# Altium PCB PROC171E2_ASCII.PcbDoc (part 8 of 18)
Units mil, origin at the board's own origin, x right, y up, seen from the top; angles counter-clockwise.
Board outline 7700 x 2300 mil, 6 copper layers (Top Layer, GND 1, SIG 1, SIG 2, GND 2, Bottom Layer), stack 61.062 mil thick; 938 components, 688 nets, 11933 pads, 1723 vias.
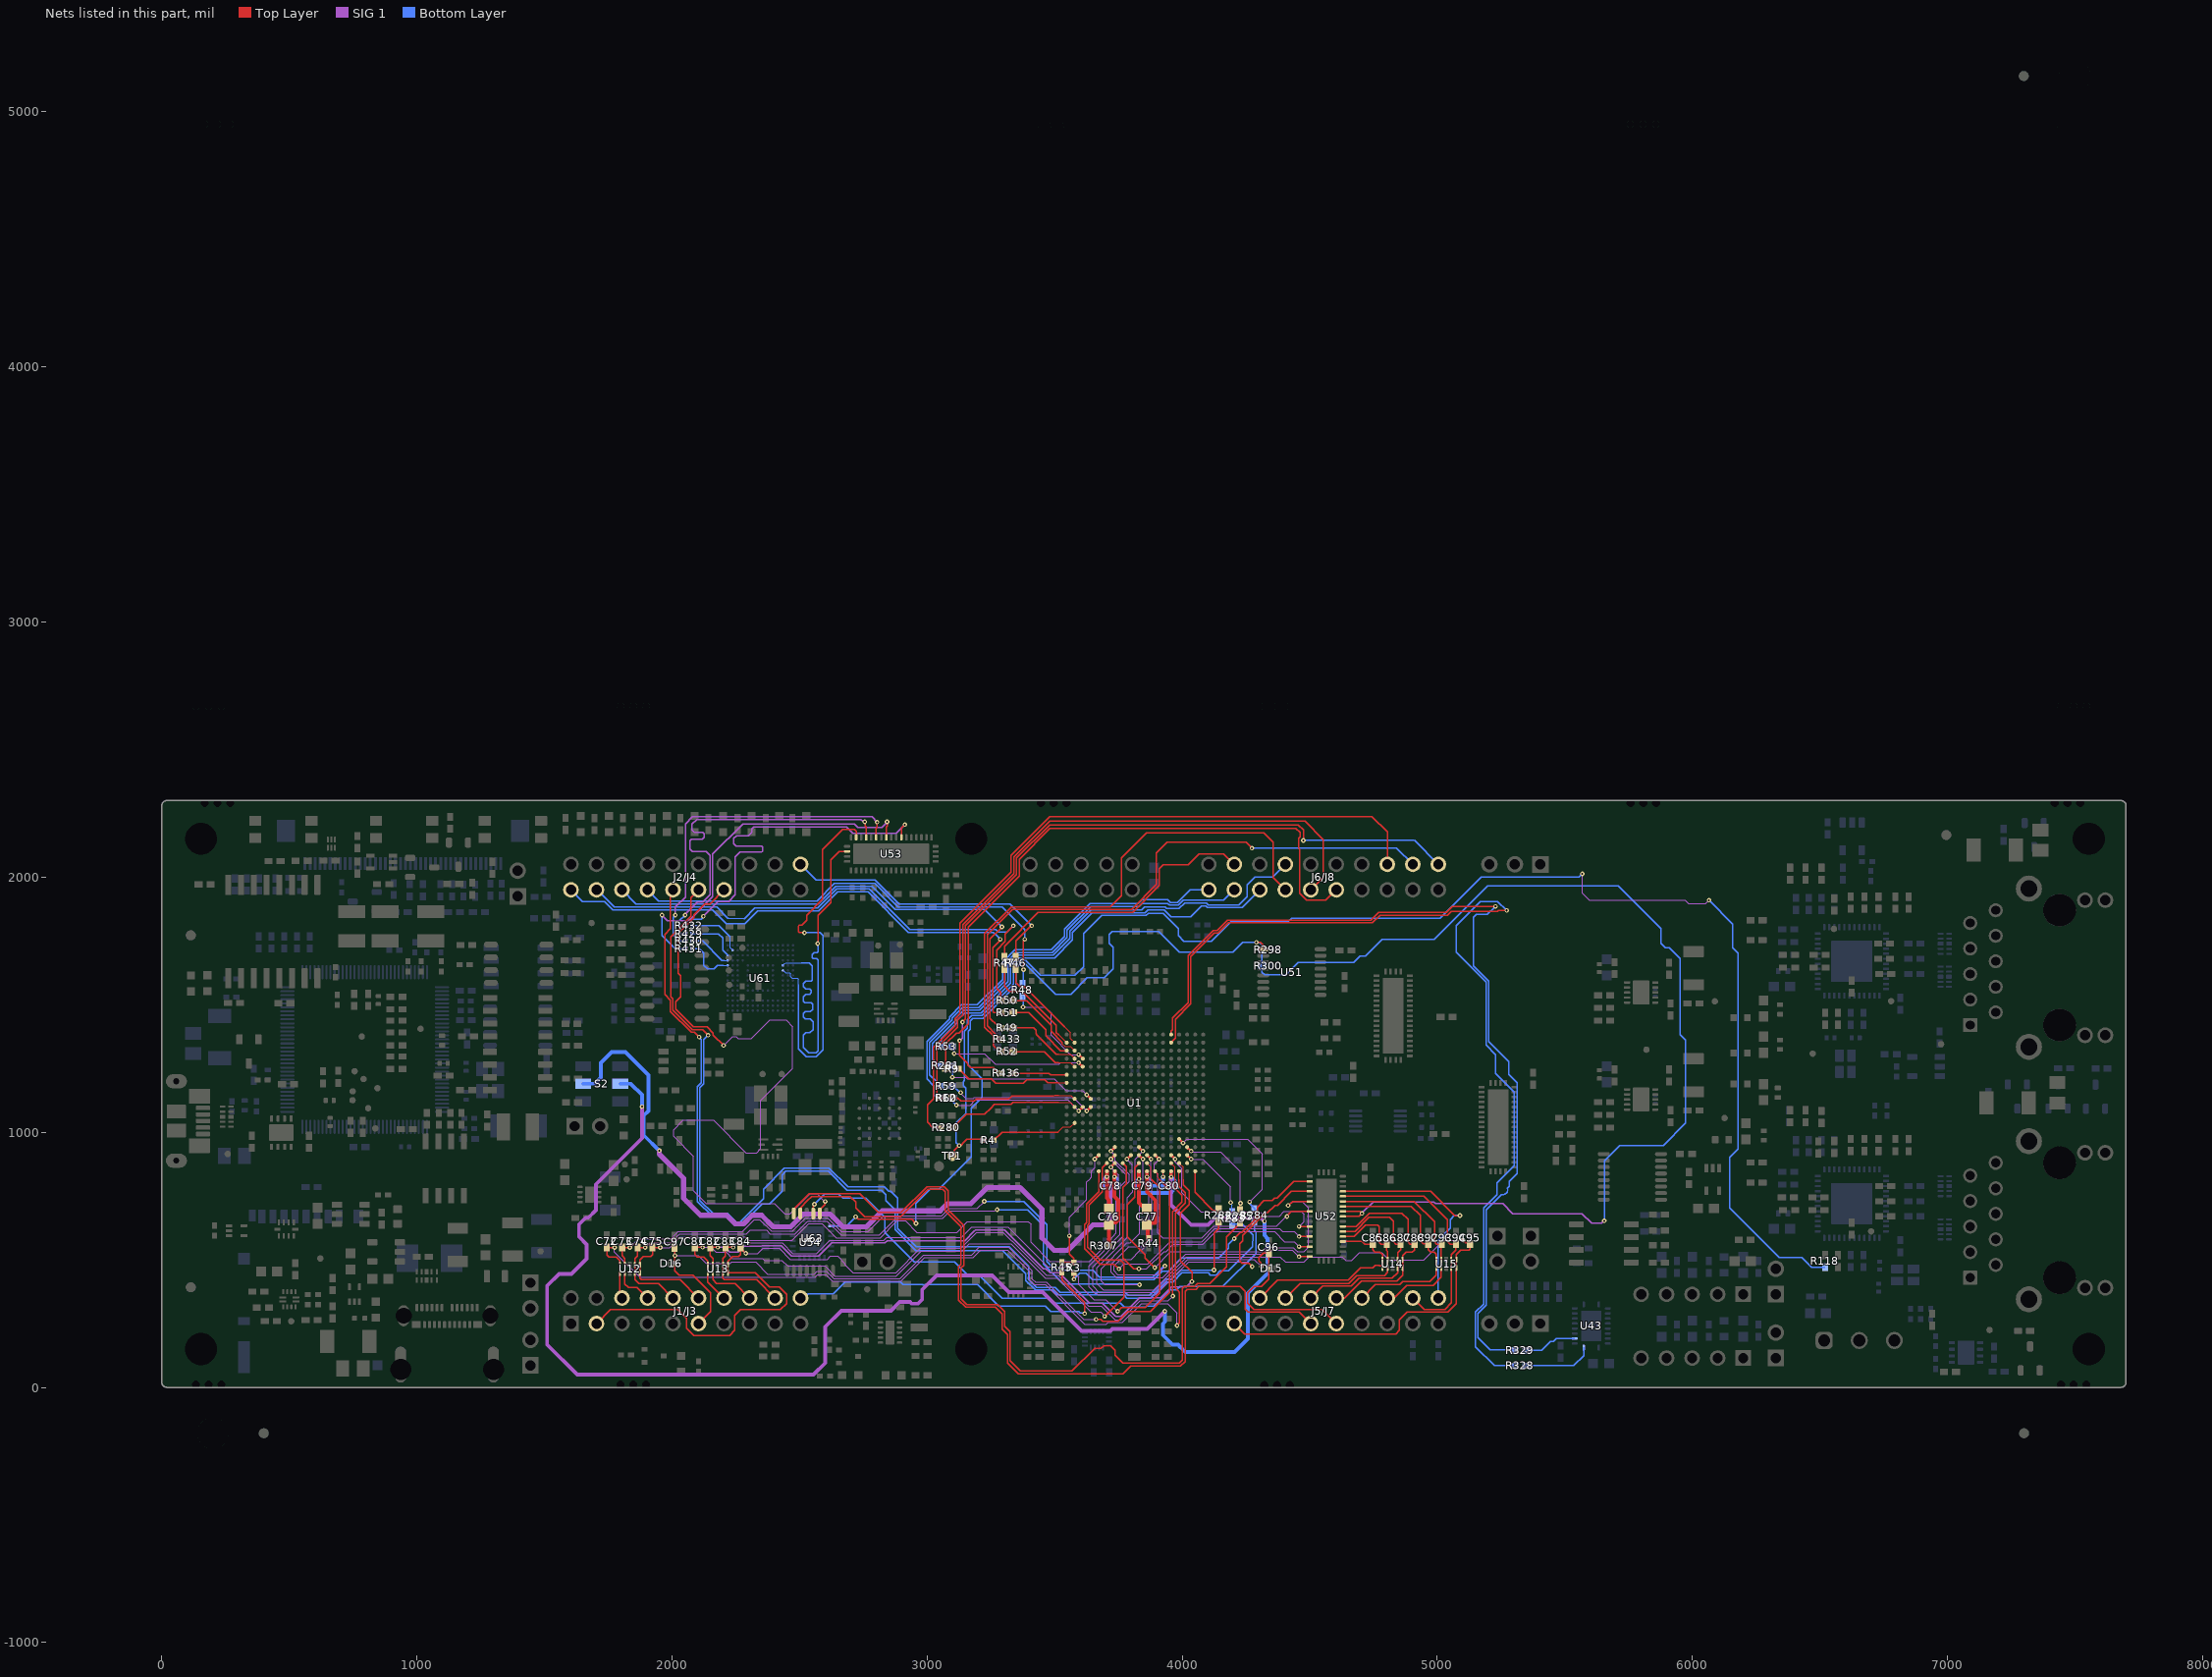
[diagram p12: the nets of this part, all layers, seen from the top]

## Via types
v1: diameter 18, hole 8, Top Layer to Bottom Layer, tented both sides, 1592 vias
v2: diameter 19.68, hole 7.87, Top Layer to Bottom Layer, tented both sides, 104 vias
v3: diameter 19.68, hole 7.87, Top Layer to Bottom Layer, 24 vias
v4: diameter 18, hole 8, Top Layer to Bottom Layer, 3 vias

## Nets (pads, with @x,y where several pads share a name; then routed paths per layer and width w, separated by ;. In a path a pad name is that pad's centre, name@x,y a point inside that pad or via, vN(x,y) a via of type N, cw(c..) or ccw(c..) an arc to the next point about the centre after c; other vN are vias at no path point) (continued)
AM263P_ADC0_AIN0: C72.1 J1/J3.23 U1.V15 U12.1 U12.10 | length 3479.2
  Top Layer w4: 3988.08,815.87 U1.V15@3988.08,847.36
  Top Layer w5.3: v1(1775,548.33) C72.1@1745,548.33 1745,519.48 1753.65,510.82 1781.73,510.82 1795.63,496.93 U12.10@1795.63,480.91 U12.1@1795.63,448.04 1795.63,358.54 J1/J3.23@1804.17,350 ; v1(3980,242.47) 3989.69,252.17 3989.69,373 3983.32,379.37 3972.78,389.91 3972.78,683.06 4012.02,722.3 4012.02,763.67 3988.08,787.62 3988.08,815.87
  SIG 1 w4.75: v1(1775,548.33) 1775,530.95 1873.95,432 2560.61,432 2571.02,442.4 2603.11,442.4 2629.31,416.21 2898.62,416.21 2990.57,508.16 3180.34,508.16 3210.71,538.54 3316.31,538.54 3401.85,453 3401.85,420.82 3420.39,402.28 3463.11,402.28 3618.67,246.72 3702,246.72 3709.39,254.12 3765.97,254.12 3840.62,328.77 3943.59,328.77 3980,292.36 v1(3980,242.47)
AM263P_ADC0_AIN1: C82.1 J1/J3.28 U1.U15 U13.2 U13.9 | length 2981.8
  Top Layer w4: U1.U15@3988.08,878.86 4003.83,863.11 4003.83,815.87
  Top Layer w5.3: v1@2180,548.85 C82.1@2150,548.85 2150,516.35 2160.31,506.03 U13.9@2160.31,481.44 U13.2@2160.31,448.56 2160.31,421.62 2175,406.94 2247.24,406.94 J1/J3.28@2304.17,350 ; 4003.98,815.87 4003.98,794.2 4028.17,770.01 4028.17,716.33 3993.84,681.99 3993.84,495.65 4038.32,451.17 4038.32,415.19 v1(4037.93,414.81)
  SIG 1 w5.3: v1(2180,548.85) 2207.48,548.85 2227,529.33 2258.52,529.33 2282.25,553.06 2350.56,553.06 2353.07,555.57 2428.12,555.57 2469.39,514.3 2574.61,514.3 2626.21,565.9 2834.71,565.9 2844.1,575.28 3148.64,575.28 3185.4,612.05 ; 3185.43,612.05 3190.42,617.03 3304.18,617.03 3423.64,497.58 3455.96,465.25 3466.49,465.25 3482.34,449.4 3517.17,449.4 3558.03,408.53 3558.81,408.53 3637.77,329.58 3687.14,329.58 3729.6,287.11 3729.6,286.79 3736.94,279.45 3738.15,279.45 3739.01,278.59 3759.86,278.59 3832.89,351.62 3915.55,351.62 3957.51,393.58 4016.7,393.58 v1(4037.93,414.81)
AM263P_ADC0_AIN2: U1.T14 U52.32 | length 790.2
  Top Layer w5.3: v1(4458.39,630.63) U52.32@4500.04,630.63
  Top Layer w10: U1.T14@3956.58,910.35 v1(3972.33,894.61)
  SIG 1 w4.75: v1(3972.33,894.61) 3972.33,885.08 3999.43,857.98 3999.43,762.5 4073.08,688.86 4305.29,688.86 4323.32,670.83 4381.38,670.83 4399.8,689.25 4465.75,689.25 4477.03,677.97 4477.03,649.27 v1(4458.39,630.63)
AM263P_ADC0_AIN2_LIN1_TXD: C88.1 J5/J7.66 U14.5 U14.6 U52.7 | length 857.5
  Top Layer w5.3: J5/J7.66@4604.17,350 4635.87,350 4703.06,417.19 4841.67,417.19 4864.37,439.89 U14.5@4864.37,467.68 U14.6@4864.37,500.55 4864.37,516.12 4877.56,529.31 4902.1,529.31 4910,537.21 4910,560.42 C88.1@4911.11,561.53 4893.47,561.53 4885,570 4885,658.91 4861.58,682.33 4734.12,682.33 4682.42,630.63 U52.7@4629.96,630.63
AM263P_ADC0_AIN3: C84.1 J1/J3.2 U1.U14 U13.5 U13.6 | length 3919.4
  Top Layer w4: U1.U14@3956.58,878.86 3972.4,863.04 3972.4,816.09 3972.18,815.87
  Top Layer w5.3: J1/J3.2@1704.17,250 1759.17,305 2022.85,305 2057.7,270.15 2057.7,231.07 2085.4,203.37 2226.16,203.37 2246.16,223.37 2246.16,281.95 2269.09,304.88 2424.91,304.88 2449.05,329.02 2449.05,363.97 2420.06,392.97 2382.1,392.97 2326.5,448.56 U13.5@2219.37,448.56 U13.6@2219.37,481.44 2219.37,494.53 2238.22,513.38 2261.62,513.38 2269,520.76 C84.1@2269,544.91 ; C84.1@2269,548.85 C84.1@2269,544.91 ; v1(2289.41,525.59) 2288.33,525.59 C84.1@2269,544.91 ; v1(3963.8,357.77) 3962.18,359.38 3962.18,688.13 3999.52,725.47 3999.52,753.11 3972.18,780.46 3972.18,815.87
  SIG 1 w4.75: v1(2289.41,525.59) 2290.99,524.01 2336.11,524.01 2357.35,545.25 2420.66,545.25 2463.73,502.18 2609.18,502.18 2621.48,514.47 2649.1,514.47 2679.36,484.22 2679.36,479.45 2709.61,449.2 2878,449.2 2973.79,544.99 3132.98,544.99 3194.7,606.71 3297.81,606.71 3330.67,573.85 3332.76,573.85 3467.54,439.08 3512.89,439.08 3632.71,319.25 3682.55,319.25 3707.8,293.99 cw(c3696.42,278.47) 3711.94,289.86 3737.63,264.17 3760.04,264.17 3834.87,338.99 3944.78,338.99 3963.56,357.77 v1(3963.8,357.77)
AM263P_ADC1_AIN0: C73.1 J1/J3.24 U1.T11 U12.2 U12.9 | length 3536.9
  Top Layer w5.3: v1(1835,548.33) C73.1@1805,548.33 1805,515.82 1815.31,505.51 1815.31,405.72 1830,391.04 1863.14,391.04 J1/J3.24@1904.17,350
  Top Layer w10: U1.T11@3862.09,910.35 v1(3877.84,894.61)
  SIG 1 w4.75: v1(1835,548.33) 1868.5,581.83 1994.64,581.83 2024.06,611.25 2276.97,611.25 2322.58,656.86 2344.56,656.86 2389.37,612.05 2472.24,612.05 2522.24,662.05 2612.21,662.05 2662.21,612.05 2662.78,612.05 2663.06,611.76 2769.52,611.76 2830.68,672.92 3058.06,672.92 3086.52,701.38 3196.54,701.38 v1(3224.39,729.23) ; v1(3877.84,894.61) 3877.84,813.9 3879.92,811.83 3881.31,810.44 3881.31,806.5 3881.26,782 3880.81,578.66 3880.8,576.7 3841.02,536.92 3835.88,536.92 3799.98,501.02 3757.27,501.02 3738.02,481.78 3736.78,480.54 3732.87,476.63 3732.87,456.31 3747.29,441.9 3900.58,441.9 3932.06,473.38 v1(3932.06,475.69)
  Bottom Layer w5.3: v1(3224.39,729.23) 3378.99,729.23 3469.57,638.65 3469.57,493.7 3504.61,458.66 3649.62,458.66 3673.9,434.38 3675.46,432.83 3732.26,432.83 ccw(c3735.54,452.07) 3738.82,432.83 3778.57,432.83 ccw(c3781.85,452.07) 3785.13,432.83 3884.32,432.83 3922.93,471.44 3924.38,471.44 3928.62,475.69 v1(3932.06,475.69)
AM263P_ADC1_AIN1: C83.1 J1/J3.29 U1.U11 U13.4 U13.7 | length 2844.6
  Top Layer w4: U1.U11@3862.09,878.86 3877.84,863.11 3877.84,818.36 3880.34,815.87
  Top Layer w5.3: v1@2240,548.85 C83.1@2210,548.85 2210,515.31 2199.68,505 U13.7@2199.68,481.44 U13.4@2199.68,448.56 2199.68,428.15 2205,422.84 2331.34,422.84 J1/J3.29@2404.17,350 ; v1(3747.1,298.12) 3761.59,312.6 3854.57,312.6 3912.24,370.28 3912.24,600.79 3912.15,600.88 3912.15,717.06 3912.24,717.15 3912.24,782 3912.24,783.96 3880.34,815.87
  SIG 1 w4.75: v1(2240,548.85) 2257.57,566.42 2296.49,566.42 2296.98,565.94 2432.36,565.94 2473.67,524.63 2567.66,524.63 2619.26,576.22 2830.43,576.22 2841.61,587.4 3134.6,587.4 3175.66,628.47 3317.88,628.47 3473.79,472.55 3554.06,472.55 3574.45,452.16 3594.84,431.77 3594.84,403.13 3653.65,344.32 3700.9,344.32 v1(3747.1,298.12)
AM263P_ADC1_AIN2: U1.T12 U52.29 | length 973.5
  Top Layer w5.3: v1(4411.13,670) 4411.13,673.36 4427.46,689.69 U52.29@4500.04,689.68
  Top Layer w10: U1.T12@3893.59,910.35 v1(3909.34,894.61)
  SIG 1 w4: 3890.46,850 3890.46,874.7 3909.34,893.58 v1(3909.34,894.61)
  SIG 1 w4.75: 3890.46,850 3904.9,835.56 3904.9,605 3923.79,586.11 4077.9,586.11 4123.81,632.03 4369.81,632.03 4407.78,670 v1(4411.13,670)
AM263P_ADC1_AIN2_SDFM0_D2: C92.1 J5/J7.67 U15.1 U15.10 U52.11 | length 926.3
  Top Layer w5.3: U52.11@4629.96,709.37 4897.79,709.37 4933.44,673.72 4933.44,574.11 4945.18,562.38 C92.1@4965,562.38 4965,540 4975,530 4988.59,530 4996.03,522.56 U15.10@4996.03,500.69 U15.1@4996.03,467.82 4996.03,440.53 4970.21,414.7 4865.21,414.7 4852.93,402.43 4756.6,402.43 J5/J7.67@4704.17,350
AM263P_ADC1_AIN3: C97.1 D16.1 J1/J3.6 U1.V12 | length 3134.9
  Top Layer w4: U1.V12@3893.59,847.36 3905,835.95 3905,822.02 3911.16,815.87
  Top Layer w5.3: C97.1@2010,547.76 2011.57,546.19 v1(2011.57,516.57) 2011.04,516.04 2011.04,490.55 2010.51,490.03 2010.51,457.6 2028.08,440.03 2082.25,440.03 2151,371.28 2151,296.83 J1/J3.6@2104.17,250 ; v1(3662.42,266.64) 3680.64,266.64 3688.33,258.95 3748.71,258.95 3787.78,298.02 3876.43,298.02 3951.58,373.17 3951.58,775.44 3911.16,815.87
  SIG 1 w4.75: v1(2011.57,516.57) 2102.93,516.57 2134.4,485.1 2227.96,485.1 2233.72,490.87 2327.69,490.87 2374.29,444.26 2557.26,444.26 2568.43,455.43 2604.93,455.43 2634.1,426.26 2894.45,426.26 2986.41,518.21 3174.31,518.21 3204.95,548.85 3320.22,548.85 3411.9,457.17 3411.9,424.98 3424.55,412.33 3467.27,412.33 3612.97,266.64 v1(3662.42,266.64)
AM263P_ADC2_AIN0: C74.1 J1/J3.25 U1.R10 U12.4 U12.7 | length 3383.5
  Top Layer w5.3: v1(1895,548.33) C74.1@1865,548.33 1865,514.79 1854.68,504.48 U12.7@1854.68,480.91 U12.4@1854.68,448.04 1854.68,422.25 1870,406.94 1947.24,406.94 J1/J3.25@2004.17,350
  Top Layer w10: U1.R10@3830.6,941.85 v1(3846.35,926.1)
  SIG 1 w4.75: v1(1895,548.33) 1914.25,567.58 1995.86,567.58 2029.49,601.2 2291.98,601.2 2307.39,616.62 2370.59,616.62 2385.21,602 2481.74,602 2531.74,652 2608.04,652 2662.39,597.65 2812.49,597.65 2818.52,603.69 2818.57,603.74 2879.32,662.87 3062.22,662.87 3090.68,691.33 3266.2,691.33 3271.36,696.5 v1(3274.95,696.5) ; v1(3832.75,402.43) 3696.51,402.43 3682.23,416.7 3682.23,464.48 3783.89,566.14 3796.1,566.14 3832.75,602.79 3832.75,778.4 3815,796.15 3815,894.76 v1(3846.35,926.1)
  Bottom Layer w5.3: v1(3274.95,696.5) 3393.99,696.5 3455.71,634.78 3455.71,484.14 3535.57,404.28 3830.9,404.28 v1(3832.75,402.43)
AM263P_ADC2_AIN1: U1.T10 U52.38 | length 1406.9
  Top Layer w5.3: v1(4458.39,512.52) U52.38@4500.04,512.52
  Top Layer w10: U1.T10@3830.6,910.35 v1(3846.35,894.61)
  SIG 1 w4: v1(3846.35,894.61) 3847,893.95 3847,815.87
  SIG 1 w4.75: 3847,815.87 3847,799.35 3870.75,775.6 3870.75,581.13 3841.51,551.89 3791.41,551.89 3722.31,482.79 3722.31,450.92 3742.28,430.95 3922.89,430.95 4013.85,521.91 4316.43,521.91 4331.45,536.92 4431.92,536.92 4456.32,512.52 v1(4458.39,512.52)
AM263P_ADC2_AIN1_MCAN5_RX: C85.1 J5/J7.63 U14.1 U14.10 U52.4 | length 781.9
  Top Layer w5.3: J5/J7.63@4304.17,350 4374.17,420 4650.72,420 4698.4,467.68 4746.98,467.68 4756.74,477.44 4772.92,477.44 4774.55,475.8 4784.34,475.8 4784.34,468.97 U14.1@4785.63,467.68 ; U52.4@4629.96,571.57 4705.59,571.57 4715.63,561.53 C85.1@4747.11,561.53 4747.11,538.93 4755.01,531.03 4774.59,531.03 4785.63,519.99 U14.10@4785.63,500.55 U14.1@4785.63,470.66
AM263P_ADC2_AIN2: U1.U10 U52.27 | length 1464.1
  Top Layer w5.3: U1.U10@3830.6,878.86 3813.63,861.89 3813.63,745.2 3785.48,717.06 3785.48,589.52 3854.78,520.22 3854.78,507.45 v1(3892.72,469.51) ; v1(4415.63,712.91) 4416.63,712.91 4432.77,729.06 U52.27@4500.04,729.06
  SIG 1 w4.75: v1(3892.72,469.51) 3955.17,531.96 4312.27,531.96 4328.49,548.18 4435.22,548.18 4442.78,540.62 ccw(c4458.39,551.89) 4447.12,536.28 4450.24,533.16 4451.63,531.77 4477.64,531.77 4495.75,549.88 4495.75,703.31 4470,729.06 4432.77,729.06 4429.21,725.5 v1(4415.63,712.91)
AM263P_ADC2_AIN2_SDFM0_CLK2: C93.1 J5/J7.68 U15.2 U15.9 U52.12 | length 879.5
  Top Layer w5.3: U52.12@4629.96,729.06 4909.46,729.06 4990,648.51 4990,570 4998.33,561.67 C93.1@5017.97,561.67 5015.48,559.18 5015.48,500.94 U15.9@5015.72,500.69 U15.2@5015.72,467.82 5015.72,432.26 4983.46,400 4879.37,400 4829.37,350 J5/J7.68@4804.17,350
AM263P_ADC2_AIN3: C95.1 J5/J7.42 U1.T9 U15.5 U15.6 | length 3425.2
  Top Layer w5.3: J5/J7.42@4204.17,250 4245.85,208.32 4836.86,208.32 4852.06,223.52 4852.06,265 4881.8,294.74 5041.07,294.74 5074.77,328.45 U15.5@5074.77,467.82 U15.6@5074.77,500.69 5074.77,519.94 5092.55,537.72 5123.8,537.72 5128.54,542.46 C95.1@5128.54,561.67 5124.09,566.12 5111.88,566.12 v1(5101.72,576.29)
  Top Layer w10: v1(3783.35,894.61) U1.T9@3799.1,910.35
  SIG 1 w4.75: v1(3783.35,894.61) 3804.95,873.01 3804.95,791.99 3806.82,790.12 3806.82,766.43 3785,744.61 3785,587.4 3665.68,468.08 3665.68,406.97 3689.91,382.74 3888.69,382.74 3926.85,420.9 3927.05,420.9 4018.01,511.86 4384.34,511.86 4404.26,491.94 4478.29,491.94 4498.01,511.66 4627.69,511.66 4641.95,497.4 4664.13,497.4 4695.15,528.42 4781.94,528.42 4810.84,499.52 4947.63,499.52 5024.4,576.29 v1(5101.72,576.29)
AM263P_ADC3_AIN0: C75.1 J1/J3.26 U1.U7 U12.5 U12.6 | length 2824
  Top Layer w5.3: v1(1954,548.33) C75.1@1924,548.33 1924,520.24 1916.62,512.86 1887.02,512.86 1874.37,500.2 U12.6@1874.37,480.91 U12.5@1874.37,448.04 1874.37,428.47 1880,422.84 2031.34,422.84 J1/J3.26@2104.17,350
  Top Layer w10: v1(3720.36,863.11) U1.U7@3736.11,878.86
  SIG 1 w4: v1@3720.36,862.49 v1(3720.36,863.11)
  SIG 1 w4.75: v1(1954,548.33) 1990.82,548.33 2032.75,590.25 2286.87,590.25 2301.14,575.99 2469.94,575.99 2535.9,641.95 2588.9,641.95 2596.8,634.06 2644.35,586.5 2817.16,586.5 2883.49,652.82 2914.87,652.82 2959.62,608.07 3116.64,608.07 3157.14,648.57 3397.39,648.57 3407.02,638.93 3407.02,567.96 3481,493.99 3637.06,493.99 3695.11,552.04 3741.83,604.69 3741.83,786.42 3750.08,794.67 3750.08,832.77 v1@3720.36,862.49
AM263P_ADC3_AIN1: U1.U8 U52.36 | length 1218
  Top Layer w5.3: U1.U8@3767.61,878.86 3782.13,864.33 3782.13,798.59 3768.05,784.5 3768.05,506.27 3809.61,464.7 v1(3830.03,464.7) ; v1(4458.39,551.89) U52.36@4500.04,551.89
  SIG 1 w4.75: v1(3830.03,464.7) 3860.69,464.7 3928.78,532.8 3936.72,532.8 3965.01,561.09 4081.3,561.09 4130.17,609.96 4136.7,609.96 4136.84,610.1 4362.33,610.1 4401.28,571.14 4439.14,571.14 v1(4458.39,551.89)
AM263P_ADC3_AIN1_MCAN5_TX: C86.1 J5/J7.64 U14.2 U14.9 U52.5 | length 812.1
  Top Layer w5.3: J5/J7.64@4404.17,350 4462.03,407.86 4653.57,407.86 4684.1,438.39 4792.53,438.39 4805.31,451.17 U14.2@4805.31,467.68 U14.9@4805.31,500.55 4805.31,533.2 4802.11,536.4 C86.1@4802.11,561.53 4780.42,561.53 4772.38,569.58 4772.38,630 4765.84,636.54 4719.02,636.54 4673.74,591.26 U52.5@4629.96,591.26
AM263P_ADC3_AIN2: U1.T7 U52.25 | length 1819.4
  Top Layer w5.3: v1(4274.32,473.35) 4274,473.35 4262.17,485.18 4235.93,485.18 4226.54,494.58 4226.54,563.49 4237.5,574.46 4237.5,595.21 4325.55,683.26 4333.87,683.26 4364,713.38 4373.5,713.38 4428.54,768.43 U52.25@4500.04,768.43
  Top Layer w10: v1(3720.36,894.61) U1.T7@3736.11,910.35
  SIG 1 w4.75: v1(3720.36,894.61) 3720.36,893.05 3781.11,832.3 3781.11,811.39 3756.08,786.36 3756.08,598.79 3634.41,477.12 3634.41,392.96 3658.26,369.11 3664.2,369.11 3670.66,362.64 3897.22,362.64 4026.33,491.76 4255.91,491.76 v1(4274.32,473.35)
AM263P_ADC3_AIN2_SDFM0_D3: C94.1 J5/J7.69 U15.4 U15.7 U52.13 | length 987.1
  Top Layer w5.3: U52.13@4629.96,748.74 4948.18,748.74 5040.31,656.61 5040.31,573.23 5051.87,561.67 C94.1@5073,561.67 5073,538 5055.09,520.09 U15.7@5055.09,500.69 U15.4@5055.09,467.82 5055.09,331.25 5029.53,305.69 4948.48,305.69 J5/J7.69@4904.17,350
AM263P_ADC3_AIN3: C96.1 D15.2 J5/J7.46 U1.R7 | length 2087.9
  Top Layer w5.3: v1(4310.31,473.53) 4307.89,475.96 4307.89,487.83 4300.31,495.4 4300.31,508.74 4317.89,526.31 C96.1@4339.72,526.31 4339.72,467.6 D15.2@4338.78,466.66 4338.78,423.78 4310,395 4282.16,395 4257.41,370.25 4257.41,329.77 4281.66,305.53 4548.64,305.53 J5/J7.46@4604.17,250
  Top Layer w10: v1(3720.36,926.1) U1.R7@3736.11,941.85
  SIG 1 w4: v1(3720.36,926.1) 3736.86,909.61 3736.86,888.39 3791.97,833.28 3791.97,815.87 3791.97,808.04
  SIG 1 w4.75: 3791.97,808.04 3768.32,784.39 3768.32,590.88 3650,472.55 3650,397.52 3672.37,375.15 3683.29,375.15 3685.75,372.69 3893.06,372.69 4022.17,501.81 4282.04,501.81 v1(4310.31,473.53)
AM263P_ADC4_AIN0: C81.1 J1/J3.27 U1.U6 U13.1 U13.10 | length 2852.5
  Top Layer w5.3: v1@2120,548.85 C81.1@2090,548.85 2090,520 2098.65,511.35 2124.65,511.35 2140.63,495.36 U13.10@2140.63,481.44 U13.1@2140.63,448.56 2140.63,413.54 J1/J3.27@2204.17,350 ; v1(3696.42,278.47) 3771.65,353.7 3771.65,485.44 3757.09,500 3679.58,500 3629.29,550.3 3629.29,634.29 3635.93,640.93 3635.93,714.5 3687.64,766.21 3687.64,861.89 U1.U6@3704.61,878.86
  SIG 1 w4.75: v1(2120,548.85) 2152.78,548.85 2172.03,529.6 2212.13,529.6 2236.64,505.09 2355.91,505.09 2363.18,497.82 2430.85,497.82 2452.96,475.71 2598.87,475.71 2638.27,436.31 2879.32,436.31 2977.54,534.52 3136.92,534.52 3166.2,563.8 3288.62,563.8 ccw(c3290.44,582.96) 3292.26,563.8 3328.6,563.8 3463.88,428.52 3509.24,428.52 3643.25,294.5 3680.39,294.5 v1(3696.42,278.47)
AM263P_ADC4_AIN1: U1.V5 U52.34 | length 1318.7
  Top Layer w5.3: U1.V5@3673.12,847.36 3673.12,766.68 3625.33,718.89 3625.33,645.32 3618.69,638.68 3618.69,544.2 3680.24,482.64 3733.79,482.64 v1(3752.12,464.31) ; v1(4458.39,591.26) U52.34@4500.04,591.26
  SIG 1 w4.75: v1(3752.12,464.31) 3752.12,465.22 3770.85,483.95 3865.73,483.95 3952.91,571.14 4077.13,571.14 4127.98,621.98 4382.08,621.98 4393.55,610.51 4439.14,610.51 v1(4458.39,591.26)
AM263P_ADC4_AIN1_LIN1_RXD: C87.1 J5/J7.65 U14.4 U14.7 U52.6 | length 837
  Top Layer w5.3: J5/J7.65@4504.17,350 4551.43,397.26 4662,397.26 4692.53,427.79 4822.45,427.79 4844.69,450.03 U14.4@4844.69,467.68 U14.7@4844.69,500.55 4844.69,527.99 4856.7,540 C87.1@4856.7,561.53 4838.47,561.53 4827.2,572.8 4827.2,651.1 4812.48,665.82 4732.61,665.82 4677.73,610.94 U52.6@4629.96,610.94
AM263P_ADC_CAL0: U1.U16
AM263P_ADC_CAL1: U1.T15
AM263P_ADC_VREFHI_G01: C77.1 C79.1 C80.1 S2.2 U1.V10 U1.V14 | length 6106.6
  Top Layer w15: U1.V10@3830.6,847.36 3831.11,846.85 v1(3831.11,816.77) 3831.11,810.33 3830.6,809.82 3830.6,723.99 3841.97,712.62 3850.13,712.62 3853.51,709.23 C77.1@3853.51,701.07 ; v1(3956.58,825) U1.V14@3956.58,847.36
  SIG 1 w15: v1(1882.41,1100.31) 1882.41,976.67 1701.41,795.68 1701.41,783.58 cw(c1676.92,777.56) 1701.41,771.54 1701.41,740.27 cw(c1676.92,734.25) 1701.41,728.23 1701.41,693.97 1672.28,664.84 1661.43,664.84 1635.86,639.27 1635.86,590.25 1665.77,560.34 1665.77,503.94 1606.09,444.26 1557.23,444.26 1510.73,397.76 1510.73,167.42 1628.33,49.82 2555.01,49.82 2600.42,95.23 2600.42,237.51 2663.58,300.67 2858.14,300.67 2892.09,334.63 2933.05,334.63 2939.75,327.93 2964.08,327.93 2980.76,344.62 2980.76,382.28 3037.71,439.23 3254.42,439.23 3319.81,373.83 3452.61,373.83 3605.36,221.08 3719.49,221.08 3727.19,228.78 3862.37,228.78 v1(3931.79,298.19) ; v1(3956.58,825) 3956.01,824.43 3956.01,822.3 3955.63,821.92 3955.63,719.49 3956.05,719.06 3956.05,716.42 4035.38,637.09 4101.11,637.09 4128.47,664.46 4308.23,664.46 4317.03,655.65 4317.17,655.65 4321.54,651.28 v1(4322.35,651.28)
  Bottom Layer w15: S2.2@1797.54,1190 1839.19,1190 1882.41,1146.78 v1(1882.41,1100.31) ; v1(3831.11,816.77) 3823.14,808.8 3823.14,789.94 3825.13,789.94 3829.44,785.63 3829.44,771.54 3838.22,762.75 3955.21,762.75 3964,771.54 3964,785.63 3968.31,789.94 C80.1@3972.24,789.94 3972.24,809.34 v1(3956.58,825) ; v1(3931.79,298.19) 3931.79,257.01 3923.94,249.16 3923.94,204.82 3962.1,166.67 3984.03,166.67 3992.51,158.18 cw(c3979.12,137.82) 3999.49,151.21 4012.88,137.82 4204.86,137.82 4257.94,190.9 4257.94,355 4258.29,355.35 4258.29,369.71 4334.93,446.35 4334.93,583.65 4322.35,596.23 v1(4322.35,651.28)
AM263P_ADC_VREFHI_G2: C76.1 C78.1 S2.5 U1.V6 | length 3365.7
  Top Layer w15: U1.V6@3704.61,847.36 v1(3704.61,825) 3704.61,742.32 3713.32,733.62 3713.32,698.14 C76.1@3713.17,698
  SIG 1 w8: 3704.49,800.8 3707.05,798.24 ; v1@3704.49,824.87 v1(3704.61,825)
  SIG 1 w20: v1(1950.75,927.95) 1950.75,914.12 2045.27,819.6 2045.27,741.3 2112.03,674.54 2214.47,674.54 2247.99,641.02 2281.74,641.02 2315.26,674.54 2351.88,674.54 2396.69,629.72 2464.91,629.72 2514.92,679.72 2620.1,679.72 2670.39,629.44 2762.2,629.44 2824.25,691.49 3051.63,691.49 3079.45,719.31 3171.56,719.31 3235.35,783.1 3365.08,783.1 3450,698.18 3450,585.76 3498.56,537.2 3550.76,537.2 3650.66,637.09 3700.33,637.09 3715.62,652.38 3715.62,789.67 3707.05,798.24 ; 3704.49,800.8 v1@3704.49,824.87
  Bottom Layer w15: S2.5@1651.87,1190 1697.96,1190 1721.8,1213.85 1721.8,1272.05 1763.82,1314.08 1816.93,1314.08 1907.31,1223.69 1907.31,1083.75 1889.85,1066.3 1889.85,988.19 v1@1950.09,927.95 ; C78.1@3696.74,789.94 3696.74,817.13 v1(3704.61,825)
AM263P_ADC_VREFLO_G01: C77.2 C79.2 C80.2 R44.2 U1.V11 U1.V13 | length 450
  Top Layer w4: v1(3925.09,825) U1.V13@3925.09,847.36
  Top Layer w15: C77.2@3861.07,637.7 3868.69,645.32 3893.65,645.32 3894.93,646.6 3894.93,733.21 3862.67,765.48 3862.67,815.87 3862.67,824.43 v1(3862.09,825) U1.V11@3862.09,847.36 ; C77.2@3864.29,628.58 3864.29,597.52 3867.19,594.61 3867.19,586.76 R44.2@3869.54,584.42
  Bottom Layer w15: v1(3862.09,825) 3862.09,824.19 3868.43,817.85 C79.2@3868.43,789.94 C80.2@3925,789.94 3925,824.91 v1(3925.09,825)
AM263P_ADC_VREFLO_G2: C76.2 C78.2 R307.2 U1.V7 | length 362.7
  Top Layer w15: R307.2@3713.62,555 3713.17,555.45 3713.17,635.99 3724.37,647.19 3740.05,647.19 3748.83,655.98 3748.83,733.91 3734.71,748.04 3734.71,815.87 3734.71,825.81 3736.11,827.21 U1.V7@3736.11,847.36
  Bottom Layer w15: v1(3734.71,825) 3735.28,824.43 3736.68,824.43 3743.98,817.13 C78.2@3743.98,789.94
AM263P_BP_MUX_SEL: R298.2 R300.2 U51.1 U52.9 U52.10 U63.7 | length 7416.2
  Top Layer w5.3: v1(2720.04,668.83) 2730.64,658.23 2940.7,658.23 v1(2956.41,642.55) ; v1(4291.03,1744.24) 4306.84,1744.24 4317.8,1733.28 U51.1@4317.8,1717.48 ; U52.9@4629.96,670 4693.01,670 v1(4705,681.99) 4697.31,689.68 U52.10@4629.96,689.68
  SIG 1 w5.3: v1(4705,681.99) v1@4705.75,682.74 ; v1@4705.15,683.35 4748.36,726.56 4986.66,726.56 4993.16,720.06 5256.77,720.06 5296.35,680.48 5567.74,680.48 5605.21,643 5644.31,643 v1(5654.39,653.09)
  Bottom Layer w5.3: U63.7@2623.77,632.69 2683.9,632.69 v1(2720.04,668.83) ; v1@2956.39,642.57 2956.39,720.88 3011.71,776.2 3045.69,776.2 3173.69,904.21 3173.69,1094.74 3192.9,1113.95 3192.9,1114.06 3204.33,1125.49 3204.44,1125.49 3215.19,1136.24 3215.19,1209.93 3197.95,1227.17 ; 3197.82,1227.05 3161.21,1263.66 3161.21,1396.25 3169.22,1404.26 3169.22,1436.23 3179.91,1446.92 3219.93,1446.92 3348.77,1575.76 3348.77,1644.44 3366.83,1662.51 3382.13,1662.51 3503.4,1541.24 3562.92,1541.24 3627.8,1606.12 3694.35,1606.12 3729.57,1641.35 3729.57,1724.32 3713.62,1740.28 3713.62,1775.16 3725.58,1787.12 3909.07,1787.12 3989.71,1706.48 4199.68,1706.48 4237.44,1744.24 v1(4291.03,1744.24) 4291.19,1744.08 4302.68,1744.08 4312.89,1733.88 R300.2@4312.89,1652.52 4312.89,1626.91 4323,1616.79 4405.75,1616.79 4453.96,1665 4672.04,1665 4697.54,1690.5 4717.5,1690.5 4783.54,1756.54 4988.39,1756.54 5197.32,1965.47 5710.03,1965.47 5876.5,1799 5876.5,1741.5 5894,1724 5908.74,1724 5951,1681.74 5951,1383.57 5972.85,1361.72 5972.85,1035.35 5885.7,948.2 5714.61,948.2 5655,888.59 5655,653.69 v1(5654.39,653.09)
AM263P_CLKOUT0: R4.2 R118.1 TP1.1 | length 5932.9
  Top Layer w5.3: TP1.1@3099.06,906.94 3105.3,913.18 3105.3,929.18 3126.31,950.19 3134.53,950.19 3142.67,958.33 3156.79,972.45 3217.83,972.45 R4.2@3221.22,969.06
  SIG 1 w4.75: v1(5568.36,2012.89) 5568.36,1937.74 5596.85,1909.25 5970.75,1909.25 5984.25,1895.75 6051.33,1895.75 v1(6065,1909.42)
  Bottom Layer w5.3: v1(3126.08,947.76) 3114.14,959.7 3114.14,1035.32 3151.1,1072.28 3151.1,1172.52 3141.87,1181.75 3141.87,1197.92 3146.71,1202.76 3146.71,1396.74 3158.48,1408.5 3158.48,1440.98 3175.02,1457.52 3215.54,1457.52 3338.17,1580.15 3338.17,1648.83 3362.44,1673.11 3386.52,1673.11 3444.63,1615 3580,1615 3613.9,1648.9 3613.9,1778.89 3684.53,1849.52 3858.86,1849.52 3867.49,1858.15 3925.03,1858.15 3985,1798.18 3985,1771.15 4007.27,1748.88 4114.83,1748.88 4190.89,1824.93 4415.03,1824.93 4429.02,1838.92 5010.58,1838.92 5172.52,2000.87 5556.33,2000.87 v1(5568.36,2012.89) ; v1(6065,1909.42) 6157.91,1816.51 6157.91,1723.92 6179.31,1702.52 6179.31,934.87 6146.9,902.46 6146.9,703.11 6340.09,509.92 6428.75,509.92 6467.3,471.38 R118.1@6520,471.38
AM263P_CLKOUT0_R: R4.1 U1.M2 | length 345.9
  Top Layer w4: 3515.64,1002.84 3533.39,1020.59 3562.88,1020.59 U1.M2@3578.63,1036.34
  Top Layer w5.3: R4.1@3260.59,969.06 3262.56,969.06 3293.6,1000.11 3512.9,1000.11 3515.64,1002.84
AM263P_DAC_OUT1: J1/J3.30 R45.1 | length 1389.1
  Top Layer w5.3: R45.1@3528.72,450.24 3528.72,420.58 3617.7,331.6 v1(3617.7,289.13)
  Bottom Layer w5.3: J1/J3.30@2504.17,350 2518.44,350 2535.14,366.7 2632.43,366.7 2634.54,368.81 2634.76,368.81 2679.17,413.22 2895.74,413.22 2904.92,404.04 2906.48,402.48 2981.77,402.48 ccw(c2985.63,421.62) 2989.5,402.48 3197.32,402.48 3281.82,317.98 3464.43,317.98 3484.36,298.05 3594.59,298.05 3601.08,291.56 3615.27,291.56 v1(3617.7,289.13)
AM263P_DAC_OUT2: R3.1 U52.23 | length 1161.3
  Top Layer w5.3: R3.1@3575.19,448.84 3575.59,448.44 v1(3575.59,423.8) ; v1(4204.17,583.26) 4227.69,606.78 4234.08,606.78 4294.17,666.87 4294.17,705.98 4319.99,731.8 4352.43,731.8 4362.41,741.77 4371.91,741.77 4437.93,807.8 U52.23@4500.04,807.8
  Bottom Layer w5.3: v1(3575.59,423.8) 3598.94,447.15 3623.25,447.15 3648.44,421.95 3881.74,421.95 3882.02,422.23 3888.71,422.23 3922.15,455.67 3945.93,455.67 3996.61,506.35 4142.26,506.35 4182.08,546.17 4182.08,561.18 v1(4204.17,583.26)
AM263P_DAC_OUT2_SDFM0_CLK3: J5/J7.70 U52.14 | length 870.1
  Top Layer w5.3: U52.14@4629.96,768.43 4973.69,768.43 5069.14,672.97 5087.95,672.97 v1(5088.74,673.76)
  Bottom Layer w5.3: J5/J7.70@5004.17,350 5004.17,577.29 5050.6,623.72 5050.6,657.19 5067.17,673.76 v1(5088.74,673.76)
AM263P_DAC_OUT_R: R3.2 R45.2 U1.T5 | length 523.2
  Top Layer w5.3: R45.2@3528.72,489.61 3573.8,489.61 R3.2@3574.55,488.85 ; v1(3557.81,594.15) 3557.81,521.62 3574.55,504.87 R3.2@3574.55,488.85 ; R3.2@3575.19,488.21 R3.2@3574.55,488.85
  Top Layer w10: v1(3657.37,894.61) U1.T5@3673.12,910.35
  SIG 1 w4: 3636.96,815.87 3645,823.91 3645,848.34 3657.37,860.71 v1(3657.37,894.61)
  SIG 1 w4.75: v1(3557.81,594.15) 3557.81,667.03 3626.32,735.54 3626.32,805.23 3636.96,815.87
AM263P_EMMC0_CLK_MUX: U53.40 U61.M5 | length 1573.6
  Top Layer w5.3: v1(2571.22,1739.68) 2573.03,1741.49 2573.03,1850.25 2622.73,1899.94 2622.73,2067.48 2656.13,2100.88 U53.40@2686.56,2100.88
  Bottom Layer w3.4: U61.M5@2434.92,1654.01 2441.81,1660.91 ; 2441.9,1660.82 2444.91,1663.84 2507.2,1663.84 2508.01,1663.03
  Bottom Layer w5.3: 2508.01,1663.77 2538.54,1663.77 2549.68,1652.63 2549.68,1595.66 2545.97,1591.95 2523.93,1591.95 2515.62,1583.65 2515.62,1570.62 2523.76,1562.48 2540.29,1562.48 2546.85,1555.93 2546.85,1547.44 2540.45,1541.04 2525.35,1541.04 2515.62,1531.32 2515.62,1514.38 2521.81,1508.19 2544.98,1508.19 2551.21,1501.96 2551.21,1481.05 2542.67,1472.51 2522.88,1472.51 2515.62,1465.26 2515.62,1451.41 2523.33,1443.7 2542.3,1443.7 2552.83,1433.16 2552.83,1402.76 2540.64,1390.57 2524.86,1390.57 2515.62,1381.33 2515.62,1331.69 2536.8,1310.52 2564.39,1310.52 2573.03,1319.16 2573.03,1674.92 2567.28,1680.68 2554.27,1680.68 2549.98,1684.97 2549.98,1697.11 2556.63,1703.76 2568.77,1703.76 2573.03,1708.03 2573.03,1737.87 v1(2571.22,1739.68)
AM263P_EMMC0_CMD_MUX: U53.37 U61.M6 | length 1580.7
  Top Layer w5.3: v1(2519.19,1782.19) 2499.54,1782.19 2495.38,1786.35 2495.38,1808.38 2498.48,1811.49 2509.14,1811.49 2528.12,1830.46 2528.12,1850.31 2590.93,1913.12 2590.93,2107.74 2669.77,2186.59 2714.68,2186.59 2721.99,2179.27 U53.37@2721.99,2156
  Bottom Layer w3.4: U61.M6@2435.29,1634.18 2444.97,1624.5 2460.46,1624.5 2464.47,1620.49 ; 2464.43,1620.49 2464.43,1610.75 2464.46,1610.71 2464.46,1610.57 2470.22,1604.82 2491.53,1604.82 2496.52,1599.82 2496.52,1578
  Bottom Layer w5.3: 2496.52,1578 2496.52,1327.39 2527.57,1296.35 2565.21,1296.35 2591.82,1322.96 2591.82,1770.53 2580.17,1782.19 v1(2519.19,1782.19)
AM263P_EMMC0_D0: R429.1 U61.A3 | length 204.6
  Bottom Layer w5.3: R429.1@2076.59,1776.94 2182.95,1776.94 2198.63,1761.25 2198.63,1714.22 2218.38,1694.48 U61.A3@2218.38,1693.38
AM263P_EMMC0_D0_MUX: R429.2 U53.35 | length 1416.5
  Top Layer w5.3: v1@2756.13,2216.63 2758.2,2214.56 2758.2,2199.92 2761.36,2196.76 U53.35@2761.36,2156
  SIG 1 w5.3: v1(2051.87,1851.18) 2051.87,1854.41 2100.05,1902.59 2121.44,1902.59 2149.2,1930.35 2149.2,2084.53 2133.73,2100 2081.13,2100 2070.87,2110.26 2070.87,2143.34 2076.78,2149.25 2118.92,2149.25 2126.5,2156.83 2126.5,2169.06 2120.71,2174.84 2088.59,2174.84 2078.72,2184.71 2078.72,2207.57 2096.7,2225.55 2740.5,2225.55 2747,2219.06 2753.7,2219.06 v1@2756.13,2216.63
  Bottom Layer w5.3: v1(2051.87,1851.18) 2028.95,1828.26 2028.95,1785.4 2037.41,1776.94 R429.2@2056.51,1776.94
  other v1: 2755.72,2216.63
AM263P_EMMC0_D1: R430.1 U61.A4 | length 173.1
  Bottom Layer w3.4: 2204.66,1673.7 U61.A4@2218.38,1673.7
  Bottom Layer w5.3: R430.1@2076.59,1749.33 2120.2,1749.33 2195.84,1673.7 2204.66,1673.7
AM263P_EMMC0_D1_MUX: R430.2 U53.33 | length 1351.5
  Top Layer w5.3: U53.33@2800.73,2156 2800.73,2190.36 2804.26,2193.89 v1@2804.26,2216.62
  SIG 1 w5.3: v1@2013.35,1849.94 2013.35,1882.68 2052.88,1922.2 2052.88,2208.34 2080.69,2236.15 2784.6,2236.15 2804.26,2216.49 v1(2804.26,2215.39)
  Bottom Layer w5.3: v1(2013.35,1851.18) 2005.33,1843.15 2005.33,1773.06 2029.06,1749.33 R430.2@2056.51,1749.33
AM263P_EMMC0_D2: R431.1 U61.A5 | length 208.4
  Bottom Layer w3.4: 2201.3,1654.01 U61.A5@2218.38,1654.01
  Bottom Layer w5.3: R431.1@2076.59,1719.72 2107.64,1719.72 2125,1702.37 2125,1654.55 2139.29,1640.25 2164.28,1640.25 2178.04,1654.01 2201.3,1654.01
AM263P_EMMC0_D2_MUX: R431.2 U53.31 | length 1420.7
  Top Layer w5.3: U53.31@2840.1,2156 2840.1,2197.03 2843.3,2200.23 v1(2843.3,2216.63)
  SIG 1 w5.3: v1(1960.83,1851.18) 1982.17,1829.84 2066.02,1829.84 2159.8,1923.62 2159.8,2090.63 2278.18,2209.02 2714.89,2209.02 2729.36,2194.55 2822.4,2194.55 2843.3,2215.45 v1(2843.3,2216.63)
  Bottom Layer w5.3: v1(1960.83,1851.18) 1960.83,1771.62 2012.73,1719.72 R431.2@2056.51,1719.72
AM263P_EMMC0_D3: R432.1 U61.B2 | length 226.7
  Bottom Layer w3.4: 2228.53,1765.41 2228.2,1765.09 2228.2,1722.93 U61.B2@2238.07,1713.07
  Bottom Layer w5.3: R432.1@2076.59,1810.15 2183.49,1810.15 2228.22,1765.41
AM263P_EMMC0_D3_MUX: R432.2 U53.28 | length 1454.2
  Top Layer w5.3: U53.28@2899.16,2156 2899.22,2156.06 2899.22,2179.04 ; 2899.24,2179.06 2899.24,2191.91 v1(2913.24,2205.91)
  SIG 1 w5.3: v1(2122.97,1846.47) 2180.73,1904.23 2222.64,1904.23 2248.52,1930.11 2248.52,2079.98 2266.04,2097.5 2351.81,2097.5 2354.92,2100.6 2354.92,2118.44 2351.81,2121.55 2251.16,2121.55 2241.58,2131.12 2241.58,2151.45 2253.02,2162.89 2300.4,2162.89 2312.35,2174.84 2312.35,2188.42 2320.6,2196.67 2684.66,2196.67 2710.13,2171.2 2878.53,2171.2 v1(2913.24,2205.91)
  Bottom Layer w5.3: R432.2@2056.51,1810.15 2056.51,1826.67 2063.84,1834 2114.36,1834 2118.22,1837.86 2118.22,1838.28 2122.97,1843.03 v1(2122.97,1846.47)
AM263P_EPWM0_A: J2/J4.11 R46.1 | length 1153.3
  Top Layer w5.3: R46.1@3347.99,1687.24 3347.99,1750.3 v1@3407.86,1810.17
  Bottom Layer w5.3: J2/J4.11@2504.17,2050 2564.82,1989.36 2795.63,1989.36 2891.06,1893.93 3325.41,1893.93 v1(3410.06,1809.27)
AM263P_EPWM0_A_R: R46.2 U1.B2 | length 396.2
  Top Layer w4: 3538.93,1414.29 3562.88,1390.34 3562.88,1367.05 U1.B2@3578.63,1351.3
  Top Layer w5.3: R46.2@3348.42,1641.72 3348.42,1587.04 3363.41,1572.05 3381.17,1572.05 3538.93,1414.29
AM263P_EPWM0_B: J6/J8.59 R47.1 | length 1148.9
  Top Layer w5.3: R47.1@3303.11,1687.17 3303.11,1729.93 3435.86,1862.69 3805.98,1862.69 3910.48,1967.18 3910.48,2032.84 3926.33,2048.69 4024.01,2048.69 4066.36,2091.04 4163.14,2091.04 J6/J8.59@4204.17,2050
AM263P_EPWM0_B_R: R47.2 U1.B1 | length 419.9
  Top Layer w4: 3515.26,1382.42 3516.01,1382.42 U1.B1@3547.13,1351.3
  Top Layer w5.3: R47.2@3303.11,1639.93 3303.11,1572.56 3323.1,1552.57 3373.87,1552.57 3506.5,1419.93 3506.5,1391.18 3515.26,1382.42
AM263P_EPWM1_A: J2/J4.37 R48.1 | length 1820.9
  Top Layer w5.3: v1(3377.87,1637.38) 3377.87,1747.78 3383,1752.91 v1(3383,1756.35)
  Bottom Layer w5.3: J2/J4.37@1904.17,1950 1948.04,1906.14 2568.11,1906.14 2636.76,1974.78 2795.21,1974.78 2886.67,1883.33 3293.67,1883.33 3383,1794 v1(3383,1756.35) ; R48.1@3373.91,1577.15 3377.87,1581.11 v1(3377.87,1637.38)
AM263P_EPWM1_A_R: R48.2 U1.D3 | length 413.8
  Top Layer w10: v1(3594.38,1304.06) U1.D3@3610.13,1288.31
  SIG 1 w4: v1(3376.47,1490.47) 3462.55,1490.47 3486.2,1466.82 3486.2,1380.22 3562.36,1304.06 v1(3594.38,1304.06)
  Bottom Layer w5.3: R48.2@3373.91,1533.84 3376.83,1530.93 v1@3376.83,1489.38
AM263P_EPWM1_B: J2/J4.38 R49.1 | length 2036.6
  Top Layer w5.3: R49.1@3283.41,1410.1 3283.41,1411.05 3276.12,1418.34 3275.16,1418.34 3247.06,1446.45 3247.06,1758.17 v1(3293.79,1804.9)
  Bottom Layer w5.3: J2/J4.38@1804.17,1950 1858.96,1895.21 2572.18,1895.21 2641.15,1964.18 2784.11,1964.18 2875.57,1872.73 3225.96,1872.73 v1(3293.79,1804.9)
AM263P_EPWM1_B_R: R49.2 U1.D2 | length 293
  Top Layer w4: 3515.64,1305.38 3561.56,1305.38 U1.D2@3578.63,1288.31
  Top Layer w5.3: R49.2@3345.34,1409.63 3346.1,1410.39 3416.8,1410.39 3426.72,1400.47 3426.72,1385.69 3431.15,1381.26 3431.15,1380.9 3506.67,1305.38 3515.64,1305.38
AM263P_EPWM2_A: J2/J4.39 R50.1 | length 2138.2
  Top Layer w5.3: R50.1@3292.62,1515.62 3288.62,1519.62 3288.62,1547.81 3272.65,1563.78 3272.65,1714.54 3306.37,1748.26 3306.37,1777.37 v1(3338.27,1809.27)
  Bottom Layer w5.3: J2/J4.39@1704.17,1950 1706.96,1950 1774.19,1882.77 2176.41,1882.77 2219.63,1839.55 2221.17,1838.02 2223.33,1838 2282.08,1837.44 2284.3,1837.44 2325.4,1878.54 2570.5,1878.54 2645.54,1953.58 2772.57,1953.58 2931.96,1794.19 3269.36,1794.19 3279.32,1784.23 3313.22,1784.23 v1(3338.27,1809.27)
AM263P_EPWM2_A_R: R50.2 U1.C2 | length 334.9
  Top Layer w4: 3529.96,1345.78 3540.19,1335.55 3562.88,1335.55 U1.C2@3578.63,1319.8
  Top Layer w5.3: R50.2@3344.01,1519.96 3349.43,1514.54 3390.78,1514.54 3486.25,1419.07 3486.25,1396.25 3529.96,1352.54 3529.96,1345.78
AM263P_EPWM2_B: J2/J4.40 R51.1 | length 2191.6
  Top Layer w5.3: v1@3285.67,1751.24 3285.17,1751.24 3282.13,1748.2 3282.13,1747.7 3257.66,1723.23 3257.66,1472.63 3260.76,1469.53 R51.1@3291.14,1469.53
  Bottom Layer w5.3: J2/J4.40@1604.17,1950 1649.13,1905.04 1735.58,1905.04 1768.45,1872.17 2158.57,1872.17 2212.62,1818.12 2285.61,1818.12 2335.43,1867.94 2574.89,1867.94 2649.93,1942.98 2768.18,1942.98 2927.57,1783.59 3259.6,1783.59 3274.69,1768.5 v1(3286.84,1756.35)
AM263P_EPWM2_B_R: R51.2 U1.C1 | length 286
  Top Layer w5.3: R51.2@3336.88,1469.02 3398.5,1469.02 3465.77,1401.75 3465.77,1377.91 3523.87,1319.8 U1.C1@3547.13,1319.8
AM263P_EPWM3_A: J6/J8.77 R52.1 | length 2097.1
  Top Layer w5.3: R52.1@3289.68,1316.91 3280.52,1326.07 3273.27,1326.07 3259.11,1340.23 3259.11,1378.75 3225.68,1412.17 3225.68,1779.4 3330.17,1883.89 3718.55,1883.89 3761.17,1926.51 3761.17,2075 3860.61,2174.44 4319.4,2174.44 4356.72,2137.13 4356.72,1997.46 J6/J8.77@4404.17,1950
AM263P_EPWM3_A_R: R52.2 U1.E2 | length 266.6
  Top Layer w4: 3515.64,1272.56 3562.88,1272.56 U1.E2@3578.63,1256.81
  Top Layer w5.3: R52.2@3336.92,1316.91 3338.39,1315.44 3459.09,1315.44 3501.97,1272.56 3515.64,1272.56
AM263P_EPWM3_B: J6/J8.78 R53.1 | length 1605.2
  Bottom Layer w5.3: R53.1@3055.32,1341.34 3055.32,1367.06 3119.43,1431.17 3119.43,1439.67 3147.88,1468.12 3211.15,1468.12 3327.57,1584.54 3327.57,1653.22 3358.05,1683.71 3499.45,1683.71 3570.48,1754.74 3570.48,1783.55 3647.05,1860.12 3854.47,1860.12 3865.8,1871.46 3929.38,1871.46 3955.93,1844.91 4034.02,1844.91 4075.53,1886.42 4092.61,1886.42 4098.73,1880.3 4234.47,1880.3 J6/J8.78@4304.17,1950
AM263P_EPWM3_B_R: R53.2 U1.E3 | length 563.6
  Top Layer w10: v1(3594.38,1272.56) U1.E3@3610.13,1256.81
  SIG 1 w4: 3523,1272.56 v1(3594.38,1272.56)
  SIG 1 w4.75: v1(3106.04,1308.64) 3106.46,1308.22 3226,1308.22 3267.22,1267 3518,1267 3523,1272
  Bottom Layer w5.3: R53.2@3094.69,1336.34 3096.87,1336.34 3106.04,1327.18 v1(3106.04,1308.64)
AM263P_EPWM4_A: J6/J8.52 R433.1 | length 2359.5
  Top Layer w5.3: 3242.84,1781.56 3236.28,1775.01 3236.28,1416.56 3269.71,1383.14 3269.71,1379.88 3285.25,1364.34 R433.1@3289.18,1364.34 ; 3243.5,1782.22 3334.56,1873.29 3801.59,1873.29 3899.52,1971.22 3899.52,2094.24 3941.83,2136.55 4250.78,2136.55 v1(4273.66,2113.67)
  Bottom Layer w5.3: v1(4273.66,2113.67) 4840.5,2113.67 J6/J8.52@4904.17,2050
AM263P_EPWM7_B: J6/J8.51 R436.1 | length 2858.9
  Top Layer w5.3: v1(3127.18,1359.13) 3126.58,1306.53 3126.58,1302.14 3160.26,1268.46 3160.26,1263.29 3170.43,1253.12 3259.86,1253.12 3272.14,1240.83 3280.91,1240.83 R436.1@3290.61,1231.13 ; v1(3138.95,1431.58) 3150.74,1443.36 3150.74,1809.39 3350.4,2009.05 3350.4,2074.89 3480.32,2204.81 4455.44,2204.81 4475.33,2184.91 v1(4475.33,2143.82)
  SIG 1 w5.3: v1@3127.03,1356.69 3138.95,1368.61 v1(3138.95,1431.58)
  Bottom Layer w5.3: v1(4475.33,2143.82) 4909.82,2143.82 ; 4910.35,2143.82 J6/J8.51@5003.54,2050.64 ; J6/J8.51@5003.91,2050.26 J6/J8.51@5004.17,2050
AM263P_EPWM7_B_R: R436.2 U1.F1 | length 203.5
  Top Layer w5.3: R436.2@3341.77,1231.15 3477.47,1231.15 3483.99,1224.63 U1.F1@3542.6,1224.63
AM263P_EPWM9_A: J6/J8.75 R9.1 | length 2520.8
  Top Layer w5.3: R9.1@3073.65,1248.26 3073.65,1348.2 3114.71,1389.25 3125.59,1389.25 3161.34,1425 3161.34,1804.99 3361,2004.66 3361,2070.5 3481.78,2191.28 4445.73,2191.28 4461.73,2175.28 4461.73,2157.83 4455.81,2151.91 4455.81,2113.92 4459.46,2110.27 4459.46,2110.02 4460.2,2109.27 4460.2,1935.94 4487.17,1908.96 4563.14,1908.96 J6/J8.75@4604.17,1950
AM263P_EPWM9_A_R: R9.2 U1.G1 | length 460.4
  Top Layer w4: 3515.64,1193.82 U1.G1@3547.13,1193.82
  Top Layer w5.3: R9.2@3120.89,1248.26 3124.83,1248.26 3163.69,1209.4 3251.99,1209.4 3269.51,1191.88 3376.97,1191.88 3391.03,1205.95 3461.92,1205.95 3474.05,1193.82 3515.64,1193.82
AM263P_EPWM9_B: J6/J8.76 R12.1 | length 2596.5
  Top Layer w5.3: R12.1@3051.15,1135.05 3047.21,1135.05 3038.05,1144.21 3038.05,1330.44 3119.18,1411.57 3119.18,1412.19 3119.43,1412.43 3119.43,1439.67 3130.86,1451.11 3131.03,1451.11 3140.14,1460.22 3140.14,1813.78 3339.8,2013.44 3339.8,2079.28 3480.31,2219.79 4480.96,2219.79 4553.32,2147.43 4553.32,1999.15 J6/J8.76@4504.17,1950
AM263P_EPWM9_B_R: R12.2 U1.J2 | length 500.8
  Top Layer w4: 3515.64,1144.7 3564.76,1144.7 U1.J2@3578.63,1130.83
  Top Layer w5.3: R12.2@3098.4,1135.05 3118.95,1135.05 3131.99,1122 3185.18,1122 3193.51,1130.34 3320.38,1130.34 3329.02,1138.98 3329.57,1138.98 3332.02,1141.43 3496.43,1141.43 3499.7,1144.7 3515.64,1144.7
AM263P_EPWM12_A: J6/J8.53 R280.1 | length 2928.4
  Top Layer w5.3: R280.1@3049.29,1017.58 3023.7,1017.58 3001.13,1040.15 3001.13,1106.86 3025.35,1131.09 3025.35,1333.35 3108.83,1416.82 3108.83,1444.06 3129.35,1464.58 3129.35,1582.91 ; 3129.54,1582.91 3129.54,1819.46 3329.2,2019.12 3329.2,2085.2 3481.66,2237.66 4743.07,2237.66 4804.17,2176.55 J6/J8.53@4804.17,2050
AM263P_EPWM12_A_R: R280.2 U1.K2 | length 526.8
  Top Layer w4: 3515.64,1116.95 3561.01,1116.95 U1.K2@3578.63,1099.33
  Top Layer w5.3: R280.2@3100.47,1017.58 3153.11,1070.22 3165.45,1070.22 3165.64,1070.41 3225.33,1070.41 3249.85,1094.93 3250.4,1094.93 3264.61,1109.14 3329.71,1109.14 3337.7,1117.13 3512.82,1117.13 3512.99,1116.95 3515.64,1116.95
AM263P_EPWM12_B: J6/J8.57 R281.1 | length 1869.1
  Bottom Layer w5.3: R281.1@3037.12,1269.75 3020.86,1286.01 3020.86,1347.59 3108.83,1435.56 3108.83,1444.06 3143.49,1478.72 3205.72,1478.72 3316.97,1589.96 3316.97,1657.61 3353.66,1694.31 3495.06,1694.31 3559.88,1759.13 3559.88,1787.94 3642.66,1870.72 3841.76,1870.72 3853.09,1882.06 3933.77,1882.06 3939.13,1876.69 3987.7,1876.69 4009.38,1898.36 4095.89,1898.36 4103.35,1890.9 4222.75,1890.9 4254.82,1922.98 4254.82,1970 4284.82,2000 4354.17,2000 J6/J8.57@4404.17,2050 ; R281.1@3037.15,1269.75 R281.1@3044.58,1262.32
AM263P_EPWM12_B_R: R281.2 U1.J4 | length 623.1
  Top Layer w10: v1(3625.87,1146.57) U1.J4@3641.62,1130.83
  SIG 1 w4: 3578.32,1162.63 3609.82,1162.63 v1(3625.87,1146.57)
  SIG 1 w4.75: v1(3099.4,1215.66) 3152.36,1215.66 3157.66,1210.36 3497.79,1210.36 3545.53,1162.63 3578.32,1162.63
  Bottom Layer w5.3: R281.2@3097.49,1260.59 3099.4,1258.68 v1(3099.4,1215.66)
AM263P_EPWM13_A: J6/J8.79 R59.1 | length 1694.6
  Bottom Layer w5.3: R59.1@3048,1181.51 3038.84,1190.67 3038.84,1197.17 3010.26,1225.75 3010.26,1351.98 3098.23,1439.95 3098.23,1448.45 3139.1,1489.32 3201.33,1489.32 3306.37,1594.35 3306.37,1662.01 3349.27,1704.91 3490.67,1704.91 3549.28,1763.52 3549.28,1792.33 3642.63,1885.68 3831.89,1885.68 3842.6,1896.4 3943.72,1896.4 3950.24,1889.88 3985.9,1889.88 4004.98,1908.96 4163.14,1908.96 J6/J8.79@4204.17,1950
AM263P_EPWM13_A_R: R59.2 U1.K4 | length 602.9
  Top Layer w10: v1(3625.87,1083.58) U1.K4@3641.62,1099.33
  SIG 1 w4.75: v1(3131.58,1155.59) 3128.48,1155.59 3130.03,1154.04 3151.19,1132.88 3182.23,1132.88 3185.4,1136.05 3515.64,1136.05 3573.4,1136.05 3575.85,1133.61 v1(3625.87,1083.58)
  Bottom Layer w5.3: R59.2@3094.69,1181.51 3102.56,1181.51 3128.48,1155.59 v1(3131.58,1155.59)
AM263P_EPWM13_B: J6/J8.80 R60.1 | length 1676.5
  Bottom Layer w5.3: R60.1@3056.12,1135.05 3051.06,1140.11 3033.56,1140.11 3025.58,1148.09 3025.58,1183.4 2999.66,1209.32 2999.66,1356.38 3087.63,1444.34 3087.63,1452.84 3134.71,1499.92 3196.94,1499.92 3295.77,1598.74 3295.77,1666.4 3344.88,1715.51 3486.28,1715.51 3538.68,1767.91 3538.68,1796.72 3638.24,1896.28 3827.49,1896.28 3843.32,1912.1 3943.01,1912.1 3954.63,1900.48 3981.51,1900.48 4031.03,1950 J6/J8.80@4104.17,1950
AM263P_EPWM13_B_R: R60.2 U1.K3 | length 563.3
  Top Layer w10: v1(3594.38,1083.58) U1.K3@3610.13,1099.33
  SIG 1 w4.75: v1(3114.94,1106.36) 3169.92,1106.36 3189.56,1126 3515.64,1126 3551.96,1126 3579.87,1098.09 v1(3594.38,1083.58)
  Bottom Layer w5.3: R60.2@3097.46,1135.05 3102.15,1130.36 3102.15,1119.15 v1(3114.94,1106.36)
AM263P_EPWM14_A: J2/J4.35 R282.1 | length 4068
  Top Layer w5.3: J2/J4.35@2104.17,1950 2074.62,1920.45 2074.62,1846.32 1994.67,1766.37 1994.67,1531.6 2003.88,1522.4 2003.88,1478.04 2079.98,1401.94 2120.34,1401.94 v1(2141.83,1380.45) ; v1(4125,459.85) 4125,604.67 4143,622.67 R282.1@4143,651.06 ; R282.1@4141.03,653.03 R282.1@4143,655
  Bottom Layer w5.3: v1(2141.83,1380.45) v1(2141.83,1380.45) 2125,1363.69 2125,1190.1 2109.83,1174.93 2109.83,733.1 2160.62,682.31 2217.09,682.31 2251.04,648.37 2267.21,648.37 2358.7,739.86 2358.7,777.37 2440.56,859.22 2615.5,859.22 2689.43,785.29 2833.01,785.29 2849.73,768.57 2857.72,768.57 2885.15,741.15 2885.15,622.6 2956.87,550.87 3320.62,550.87 3397.72,473.77 3397.72,423.25 3428.79,392.18 3502.7,392.18 3522.4,372.48 3776.04,372.48 3788.13,360.38 3871.84,360.38 3935.32,423.87 3959.1,423.87 3994.22,458.99 4124.13,458.99 v1(4125,459.85)
AM263P_EPWM14_A_R: R282.2 U1.V17 | length 204.1
  Top Layer w5.3: U1.V17@4051.07,847.36 4051.07,763.99 4120.69,694.37 R282.2@4143,694.37
AM263P_EPWM14_B: J2/J4.36 R283.1 | length 4163.7
  Top Layer w5.3: J2/J4.36@2004.17,1950 1993.83,1939.66 1993.83,1797.86 1971.59,1775.63 1971.59,1539.69 1993.28,1518.01 1993.28,1473.65 2075.59,1391.34 2088.21,1391.34 v1(2106.62,1372.93)
  Bottom Layer w5.3: v1(2106.62,1372.93) 2106.62,1371.24 2114.4,1363.47 2114.4,1194.49 2099.23,1179.32 2099.23,728.71 2156.22,671.71 2156.83,671.71 2157.32,671.23 2213.19,671.23 2246.65,637.77 2271.6,637.77 2352.91,719.08 2382.08,719.08 2431.73,768.73 2431.73,832.09 2446.46,846.83 2612.91,846.83 2686.59,773.15 2821.31,773.15 2839.16,755.3 2839.16,731.91 2874.55,696.52 2874.55,618.2 2956.16,536.59 3296.37,536.59 3387.12,445.84 3387.12,418.86 3424.4,381.58 3490.77,381.58 3510.48,361.88 3771.65,361.88 3783.74,349.78 3876.23,349.78 3939.71,413.27 3963.49,413.27 3998.62,448.39 4102.31,448.39 4110.37,440.33 4133.09,440.33 4149.04,456.29 4181.34,456.29 4276.55,551.5 4278.1,594.96 ccw(c4258.67,596.82) 4278.19,597.04 4235.53,639.7 R283.1@4195.58,639.7
AM263P_EPWM14_B_R: R283.2 U1.T16 | length 321.7
  Top Layer w10: U1.T16@4019.57,910.35 v1(4035.32,894.61)
  SIG 1 w4.75: v1(4035.32,894.61) 4081.83,894.61 4190,786.43 v1(4190,724.36)
  Bottom Layer w4.75: v1@4192.03,723.35 4192.03,718.75 4195.58,715.19 R283.2@4195.58,686.94
AM263P_EPWM15_A: R284.1 U54.4 | length 2222
  Top Layer w5.3: U54.4@2554,681.41 2554,709.92 2558.64,714.57 v1(2558.64,718.01)
  Bottom Layer w5.3: v1(2558.64,718.01) 2598.51,757.87 2654.05,757.87 2670.73,741.18 2759.95,741.18 2835.24,665.89 2835.24,607.11 2949.85,492.5 3108.36,492.5 3164.31,436.55 3208.23,436.55 3294.99,349.78 3477.6,349.78 3497.3,330.08 3696.8,330.08 3697.02,329.85 3758.7,329.85 3773.82,314.73 3856.17,314.73 3859.42,317.98 3889.4,317.98 3952.88,381.47 3976.67,381.47 3990.48,395.28 4158.76,395.28 4288.66,525.18 4288.79,596.76 ccw(c4258.67,596.82) 4288.79,597.07 4288.7,609.21 4287.15,610.76 4283.14,614.77 R284.1@4283.14,654.64
AM263P_EPWM15_A_BP: J2/J4.34 U54.3 | length 3020.6
  Top Layer w5.3: v1(2202.56,1340.16) 2161.35,1381.37 2161.35,1388.54 2137.35,1412.54 2084.37,1412.54 2014.48,1482.43 2014.48,1511.23 2033.72,1530.48 2033.72,1613.06 2023.5,1623.28 2023.5,1778.33 2085.22,1840.06 2085.22,1851.32 2129.23,1895.33 2149.5,1895.33 J2/J4.34@2204.17,1950 ; U54.3@2579.59,681.41 2579.59,697.65 2598.97,717.04 2598.97,727.25 v1(2600.42,728.69)
  SIG 1 w4.75: v1(2202.56,1340.16) 2238.16,1375.76 2251.18,1375.76 2258.79,1368.15 2311.86,1368.15 2383.32,1439.61 2447.08,1439.61 2472.42,1414.27 2472.42,1249.49 2348.3,1125.37 2348.3,935.59 2332.34,919.63 2290.88,919.63 2162.26,1048.26 2044.3,1048.26 2006.22,1010.18 2006.22,983.52 2083.51,906.24 2083.51,771 2134.64,719.87 2400.88,719.87 2441.24,679.51 2463.31,679.51 2542.61,758.81 2568.42,758.81 2598.54,728.69 v1(2600.42,728.69)
AM263P_EPWM15_A_R: R284.2 U1.P15 | length 611.6
  Top Layer w10: U1.P15@3988.08,973.35 v1(4003.83,957.6)
  SIG 1 w4: v1(4003.83,957.6) 4018.83,972.6 4041.54,972.6
  SIG 1 w4.75: 4041.8,972.86 4255.88,972.86 4314.45,914.29 4314.45,777.05 v1(4264.2,726.8)
  Bottom Layer w5.3: v1(4264.2,726.8) 4266.63,724.37 4266.63,718.54 4282.93,702.24 R284.2@4282.93,694.37
AM263P_EPWM15_B: R285.1 U54.7 | length 3052.9
  Top Layer w5.3: U54.7@2477.23,681.41 2477.23,697.16 2538.88,758.81 2735.45,758.81 2808.71,685.56 2898.09,685.56 2999.55,787.02 3066.87,787.02 3082.49,771.39 3082.49,695.98 3143.93,634.53 3143.93,478.25 3133.45,467.77 3133.45,346.61 3155.63,324.43 3276.55,324.43 3304.62,296.36 3304.62,240.26 3325.74,219.14 3325.74,104.04 3365.93,63.85 3568.5,63.85 3657.33,152.67 3681.89,152.67 3691.98,162.76 3719.43,162.76 3736.48,145.71 3736.48,126.66 3768.64,94.5 3988.89,94.5 4000.29,105.9 4000.29,387.36 4007.93,395 4048.05,395 4060.32,407.26 4108.58,407.26 4173.1,471.79 4173.1,589.33 4226.22,642.44 R285.1@4226.22,646.38 ; R285.1@4227.03,637.96 4227.31,637.96 4235.48,646.14 R285.1@4235.48,652.05
AM263P_EPWM15_B_BP: J5/J7.45 U54.6 | length 3163.4
  Top Layer w5.3: U54.6@2502.82,681.41 2504.82,683.41 2504.82,706.02 2531.13,732.34 2547.01,748.21 2697.73,748.21 2720.3,725.64 2720.3,723.92 2720.55,723.67 2720.55,702.97 2754.69,668.83 2896.81,668.83 3004.4,776.42 3062.48,776.42 3071.89,767 3071.89,691.59 3133.33,630.14 3133.33,482.64 3122.85,472.16 3122.85,342.22 3151.24,313.83 3267.82,313.83 3294.02,287.63 3294.02,228.21 3315.14,207.08 3315.14,95.39 3357.28,53.25 3768.41,53.25 3798.5,83.34 3993.84,83.34 4012.02,101.53 4012.02,376.85 4019.57,384.4 4053.64,384.4 4064.24,395 4227.85,395 4246.81,376.04 4246.81,307.48 4259.42,294.88 4459.3,294.88 J5/J7.45@4504.17,250
AM263P_EPWM15_B_R: R285.2 U1.R16 | length 402.2
  Top Layer w4.75: R285.2@4226.22,693.62 4226.22,719.42 v1(4228.56,721.75)
  Top Layer w10: U1.R16@4019.57,941.85 v1(4035.32,926.1)
  SIG 1 w4.75: v1(4035.32,926.1) 4037.75,923.67 4151.15,923.67 4228.56,846.27 v1(4228.56,721.75)
AM263P_EQEP0_A: R328.1 U1.B14 | length 3924.8
  Top Layer w5.3: U1.B14@3956.58,1351.3 3973.55,1368.27 3973.55,1442.96 4034.3,1503.71 4034.3,1688.64 4125.91,1780.25 4141.38,1780.25 4181.91,1820.78 4745.73,1820.78 4776.05,1851.09 5040.05,1851.09 5054.73,1865.78 5236.97,1865.78 5240.75,1869.56 v1(5272.28,1869.56)
  Bottom Layer w5.3: v1(5272.28,1869.56) 5237.01,1904.82 5169.07,1904.82 5074.53,1810.29 5074.53,1704.97 5191.17,1588.33 5191.17,1341.71 5228.38,1304.5 5228.38,1230 5301.68,1156.71 5301.68,867.97 5234.87,801.16 5234.87,756.16 5181.28,702.58 5181.28,326.95 5149.33,295 5149.33,159.5 5223.84,85 R328.1@5301.38,85
AM263P_EQEP0_A_R: R328.2 U43.1 | length 273.1
  Bottom Layer w5.3: R328.2@5348.62,85 5534.13,85 5574.13,125 U43.1@5574.13,155.98
AM263P_EQEP0_B: R329.1 U1.A14 | length 3675.9
  Top Layer w5.3: U1.A14@3956.58,1382.8 3956.85,1383.06 3956.85,1396.15 3962.95,1402.25 3962.95,1447.35 4023.7,1508.1 4023.7,1693.03 4121.52,1790.85 4136.99,1790.85 4170.25,1824.11 4173.45,1827.3 4177.52,1831.38 4740.06,1831.38 4770.38,1861.69 5035.66,1861.69 5059.26,1885.3 v1(5228.38,1885.3)
  Bottom Layer w5.3: v1(5228.38,1885.3) 5196.33,1853.25 5153.42,1853.25 5141.98,1841.81 5141.98,1652.51 5201.77,1592.72 5201.77,1354.98 5279.52,1277.22 5279.52,1226.22 5312.28,1193.47 5312.28,838.75 5281.67,808.14 5281.67,787.22 5275.43,780.98 5275.43,778.78 5275.43,778.27 cw(c5256.31,774.31) 5252.35,755.19 5251.84,755.19 5191.88,695.23 5191.88,321.79 5159.93,289.84 5159.93,194.63 5207.78,146.78 5299.69,146.78 R329.1@5301.38,145.09
AM263P_EQEP0_B_R: R329.2 U43.3 | length 209.3
  Bottom Layer w5.3: R329.2@5348.62,145.09 5409.09,145.09 5443.62,179.63 5454.74,179.63 5466.52,191.41 U43.3@5538.7,191.41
